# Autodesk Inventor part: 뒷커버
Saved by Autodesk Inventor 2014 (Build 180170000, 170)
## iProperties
Created: 2026-07
Part Number: 뒷커버
Material: 일반
Document SubType Name: Modeling
Designer: dg
Density: 1 g/cm^3
Appearance: 기본값
Author: dg
Author: jhkim
Creation Date: 2026-07-02
Sending System: Autodesk Inventor 2027
Preprocessor: ST-DEVELOPER v20.1
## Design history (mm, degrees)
node "뒷커버1"
node "솔리드1"
node "기준1"
